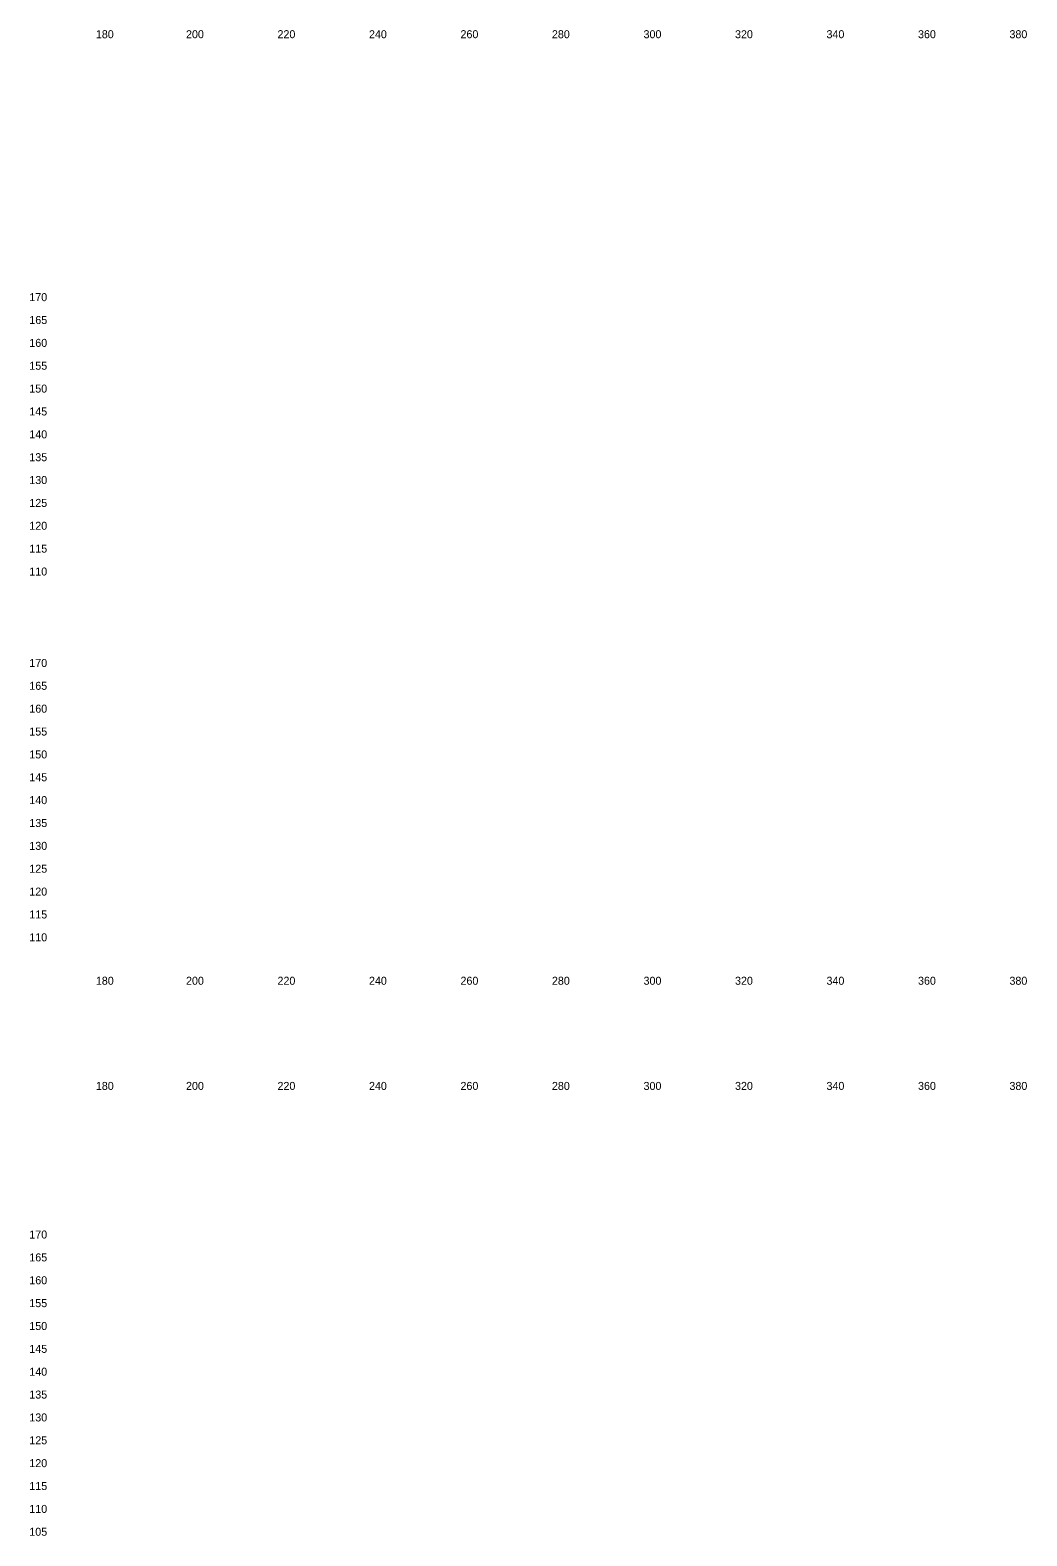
# Model space of a CAD drawing. Extents: x 21059 to 22955, y 6470 to 17494.
# Drawn here: x 21806.3 to 22024.2, y 12334.8 to 12664.1 of the extents above; entities that cross this region are included whole.
import ezdxf

# ---------------------------------------------------------------- set-up
doc = ezdxf.new("R2010")
doc.units = 0
doc.layers.add('Draft_XS_Grid', color=7, linetype='Continuous')
doc.layers.add('Draft_XS_Text', color=7, linetype='Continuous')

msp = doc.modelspace()

# ---------------------------------------------------------------- texts
at = {"layer": 'Draft_XS_Grid'}
for s, p in [('  170  ', (21804.84, 12604.84)), ('  165  ', (21804.84, 12599.84)), ('  160  ', (21804.84, 12594.84)), ('  155  ', (21804.84, 12589.84)), ('  150  ', (21804.84, 12584.84)), ('  145  ', (21804.84, 12579.84)), ('  140  ', (21804.84, 12574.84)), ('  135  ', (21804.84, 12569.84)), ('  130  ', (21804.84, 12564.84)), ('  125  ', (21804.84, 12559.84)), ('  120  ', (21804.84, 12554.84)), ('  115  ', (21804.84, 12549.84)), ('  110  ', (21804.84, 12544.84)), ('  170  ', (21804.84, 12524.84)), ('  165  ', (21804.84, 12519.84)), ('  160  ', (21804.84, 12514.84)), ('  155  ', (21804.84, 12509.84)), ('  150  ', (21804.84, 12504.84)), ('  145  ', (21804.84, 12499.84)), ('  140  ', (21804.84, 12494.84)), ('  135  ', (21804.84, 12489.84)), ('  130  ', (21804.84, 12484.84)), ('  125  ', (21804.84, 12479.84)), ('  120  ', (21804.84, 12474.84)), ('  115  ', (21804.84, 12469.84)), ('  110  ', (21804.84, 12464.84)), ('  170  ', (21804.84, 12399.84)), ('  165  ', (21804.84, 12394.84)), ('  160  ', (21804.84, 12389.84)), ('  155  ', (21804.84, 12384.84)), ('  150  ', (21804.84, 12379.84)), ('  145  ', (21804.84, 12374.84)), ('  140  ', (21804.84, 12369.84)), ('  135  ', (21804.84, 12364.84)), ('  130  ', (21804.84, 12359.84)), ('  125  ', (21804.84, 12354.84)), ('  120  ', (21804.84, 12349.84)), ('  115  ', (21804.84, 12344.84)), ('  110  ', (21804.84, 12339.84)), ('  105  ', (21804.84, 12334.84))]:
    msp.add_text(s, height=1.75, dxfattribs=at).set_placement(p)
at = {"layer": 'Draft_XS_Text'}
for s, p in [('  180  ', (21819.39, 12662.34)), ('  200  ', (21839.1, 12662.34)), ('  220  ', (21859.1, 12662.34)), ('  240  ', (21879.1, 12662.34)), ('  260  ', (21899.11, 12662.34)), ('  280  ', (21919.1, 12662.34)), ('  300  ', (21939.13, 12662.34)), ('  320  ', (21959.13, 12662.34)), ('  340  ', (21979.13, 12662.34)), ('  360  ', (21999.14, 12662.34)), ('  380  ', (22019.13, 12662.34)), ('  180  ', (21819.39, 12455.34)), ('  200  ', (21839.1, 12455.34)), ('  220  ', (21859.1, 12455.34)), ('  240  ', (21879.1, 12455.34)), ('  260  ', (21899.11, 12455.34)), ('  280  ', (21919.1, 12455.34)), ('  300  ', (21939.13, 12455.34)), ('  320  ', (21959.13, 12455.34)), ('  340  ', (21979.13, 12455.34)), ('  360  ', (21999.14, 12455.34)), ('  380  ', (22019.13, 12455.34)), ('  180  ', (21819.39, 12432.34)), ('  200  ', (21839.1, 12432.34)), ('  220  ', (21859.1, 12432.34)), ('  240  ', (21879.1, 12432.34)), ('  260  ', (21899.11, 12432.34)), ('  280  ', (21919.1, 12432.34)), ('  300  ', (21939.13, 12432.34)), ('  320  ', (21959.13, 12432.34)), ('  340  ', (21979.13, 12432.34)), ('  360  ', (21999.14, 12432.34)), ('  380  ', (22019.13, 12432.34))]:
    msp.add_text(s, height=1.75, dxfattribs=at).set_placement(p)

doc.saveas('drawing.dxf')
